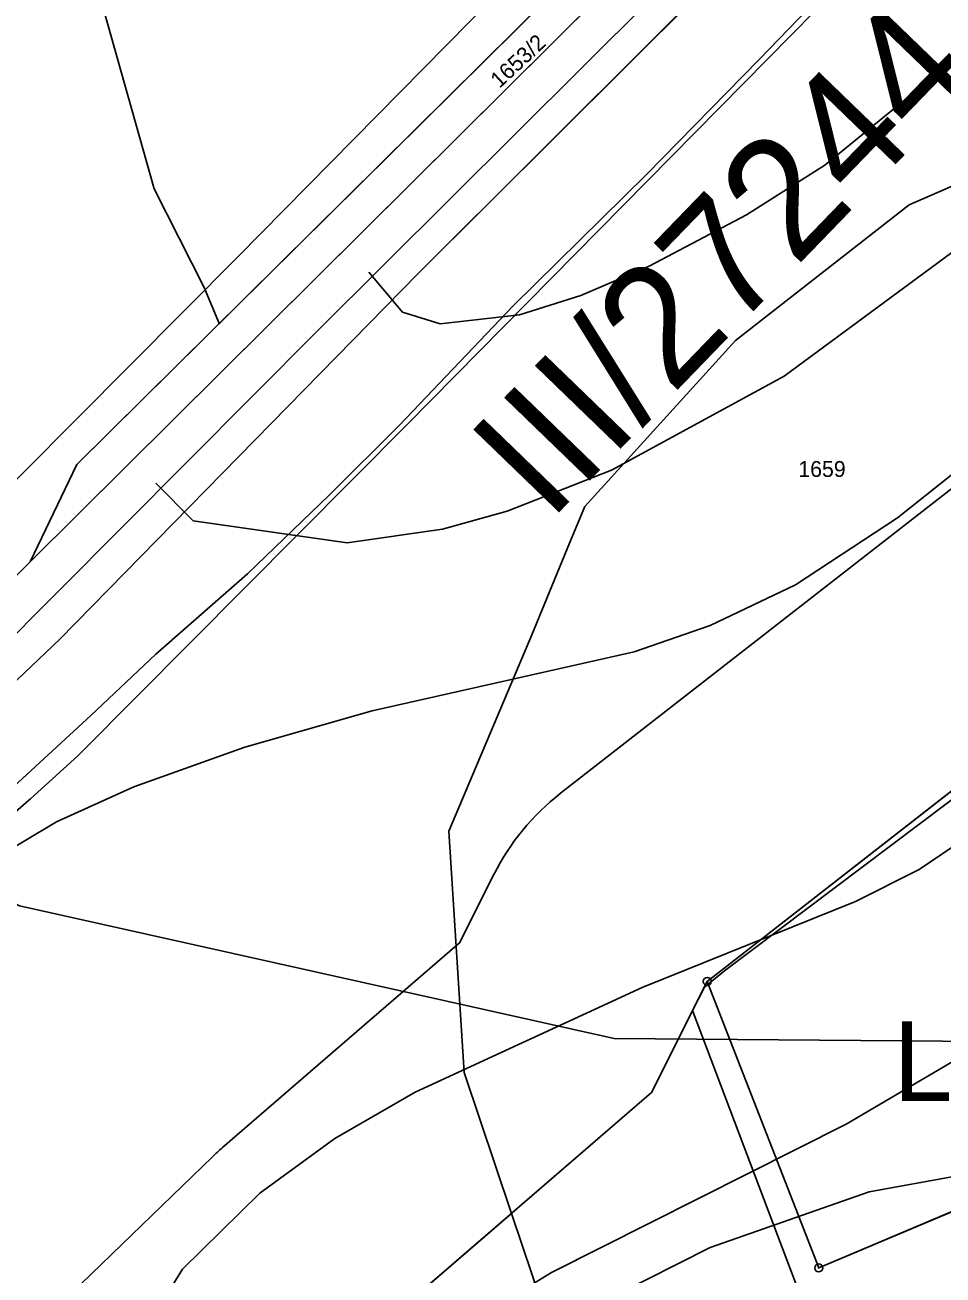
# Model space of a CAD drawing. Extents: x -706130 to -698555, y -971544 to -967260.
# Drawn here: x -704555.8 to -704440.4, y -971375.3 to -971218.1 of the extents above; entities that cross this region are included whole.
import ezdxf

# ---------------------------------------------------------------- set-up
doc = ezdxf.new("R2010")
doc.units = 0
for name, color, linetype in [('BPEJ hranice S', 7, 'Continuous'), ('BPEJ I-II trida ochrany S', 7, 'Continuous'), ('KN_Hranice_parcel', 7, 'Continuous'), ('KN_Parcelni cisla', 7, 'Continuous'), ('KN_Polygon parcely', 7, 'Continuous'), ('KN_POZEMKY_10_LESNI POZEMEK', 7, 'Continuous'), ('KN_POZEMKY_14_OSTATNI PLOCHA', 7, 'Continuous'), ('KN_POZEMKY_2_ORNA PUDA', 7, 'Continuous'), ('KN_VYUZITI_16_ostatni plocha_silnice', 7, 'Continuous'), ('KN_Značky bodu BP', 7, 'Continuous'), ('Komunikace III třídy osy S', 7, 'Continuous'), ('Komunikace popis trid a kategorie popis S', 7, 'Continuous'), ('OP lesa 30 m', 7, 'Continuous'), ('OP silnic S', 7, 'Continuous'), ('Plochy doprava silniční - silnice III třídy S', 7, 'Continuous'), ('Plochy lesní všeobecné S', 7, 'Continuous'), ('Plochy zemědělské všeobecné CELEK S', 7, 'Continuous'), ('Povodi vodniho toku S', 7, 'Continuous'), ('Regulační bloky v krajině S', 7, 'Continuous'), ('Regulační bloky zastavěné S', 7, 'Continuous'), ('Regulační kódy v krajině S', 7, 'Continuous'), ('Spoje_dálkový komunikační kabel S', 7, 'Continuous'), ('Trasy cykloturistické N', 7, 'Continuous'), ('VÝŠKOPIS_vrstevnice doplňková', 7, 'Continuous'), ('VÝŠKOPIS_vrstevnice hlavní', 7, 'Continuous'), ('VÝŠKOPIS_vrstevnice zesílená', 7, 'Continuous')]:
    doc.layers.add(name, color=color, linetype=linetype)

msp = doc.modelspace()

# ---------------------------------------------------------------- linework, layer by layer
at = {"layer": 'BPEJ hranice S'}
for points in [[(-704539.06, -971416.29), (-704539.06, -971416.29), (-704508.14, -971414.82), (-704482.74, -971402.86), (-704494.65, -971367.51), (-704500.62, -971349.8), (-704502.52, -971319.44), (-704492.08, -971294.76), (-704487.34, -971283.24), (-704485.44, -971278.63), (-704466.47, -971257.76), (-704444.65, -971240.68), (-704401.02, -971221.7), (-704353.59, -971203.67)], [(-704378.49, -971271.96), (-704407.01, -971290.68), (-704407.49, -971291.03), (-704409.78, -971292.68), (-704413.99, -971295.73), (-704433.1, -971310.81), (-704467.88, -971337.03), (-704469.91, -971338.68), (-704470.4, -971339.07), (-704471.88, -971342.01), (-704458.27, -971378), (-704455.03, -971389.82), (-704482.74, -971402.86), (-704494.65, -971367.51), (-704500.62, -971349.8), (-704502.52, -971319.44), (-704492.08, -971294.76), (-704487.34, -971283.24), (-704485.44, -971278.63), (-704466.47, -971257.76), (-704444.65, -971240.68), (-704401.02, -971221.7), (-704353.59, -971203.67)], [(-704271.03, -971209.45), (-704281.66, -971219.28), (-704342.87, -971251.11), (-704378.49, -971271.96), (-704407.01, -971290.68), (-704407.49, -971291.03), (-704409.78, -971292.68), (-704413.99, -971295.73), (-704433.1, -971310.81), (-704467.88, -971337.03), (-704469.91, -971338.68), (-704470.4, -971339.07), (-704471.88, -971342.01), (-704458.27, -971378), (-704455.03, -971389.82), (-704482.74, -971402.86), (-704508.14, -971414.82)]]:
    msp.add_lwpolyline(points, dxfattribs=at)
at = {"layer": 'BPEJ I-II trida ochrany S'}
for p, q in [((-704415.53, -971158.66), (-704506.42, -971249.39)), ((-704555.17, -971285.57), (-704441.18, -971172.34)), ((-704506.42, -971249.39), (-704551.5, -971295.37)), ((-704485.44, -971278.63), (-704466.47, -971257.76)), ((-704487.34, -971283.24), (-704485.44, -971278.63)), ((-704492.08, -971294.76), (-704487.34, -971283.24)), ((-704567.91, -971298.24), (-704555.17, -971285.57)), ((-704551.5, -971295.37), (-704580.53, -971322.96)), ((-704494.65, -971367.51), (-704500.62, -971349.8)), ((-704511.39, -971381.95), (-704494.65, -971367.51)), ((-704494.65, -971367.51), (-704494.65, -971367.51))]:
    msp.add_line(p, q, dxfattribs=at)
for points in [[(-704466.47, -971257.76), (-704444.65, -971240.68), (-704401.02, -971221.7), (-704353.59, -971203.67), (-704319.45, -971190.38)], [(-704500.62, -971349.8), (-704502.52, -971319.44), (-704492.08, -971294.76)]]:
    msp.add_lwpolyline(points, dxfattribs=at)
at = {"layer": 'KN_Hranice_parcel'}
for p, q in [((-704555.17, -971285.57), (-704441.18, -971172.34)), ((-704470.04, -971338.35), (-704409.85, -971291.43)), ((-704470.04, -971338.35), (-704456.02, -971374.37)), ((-704456.02, -971374.37), (-704407.76, -971353.94))]:
    msp.add_line(p, q, dxfattribs=at)
for points in [[(-704352.25, -971025.04), (-704354.41, -971041.91), (-704363.75, -971071.95), (-704372.53, -971093.91), (-704392.41, -971128.82), (-704407.11, -971148.63), (-704415.53, -971158.66), (-704506.42, -971249.39), (-704551.5, -971295.37), (-704580.53, -971322.96), (-704605.87, -971343.56)], [(-704441.93, -971167), (-704549.29, -971273.33), (-704555.17, -971285.57)], [(-704609.43, -971335.09), (-704585.77, -971315.95), (-704567.91, -971298.24), (-704555.17, -971285.57)], [(-704547.28, -971416.68), (-704511.39, -971381.95), (-704477.04, -971352.31), (-704470.04, -971338.35)]]:
    msp.add_lwpolyline(points, dxfattribs=at)
at = {"layer": 'KN_Polygon parcely'}
for points in [[(-704609.43, -971335.09), (-704585.77, -971315.95), (-704567.91, -971298.24), (-704555.17, -971285.57), (-704549.29, -971273.33), (-704441.93, -971167), (-704450.89, -971103.61), (-704466.38, -971059.78), (-704480.71, -970987.86), (-704567.32, -971026.96), (-704576.96, -971042.42), (-704567.8, -971056.89), (-704572.05, -971076.18), (-704593.88, -971059.39), (-704608.77, -971071.6), (-704630.27, -971084.33), (-704701.81, -971105.18), (-704664.8, -971185.41), (-704639.88, -971252.78), (-704622.91, -971298.66)], [(-704555.17, -971285.57), (-704441.18, -971172.34), (-704441.93, -971167), (-704549.29, -971273.33)], [(-704456.02, -971374.37), (-704407.76, -971353.94), (-704392.68, -971363.46), (-704385.48, -971359.18), (-704401.24, -971335.95), (-704408.17, -971319.91), (-704409.85, -971291.43), (-704470.04, -971338.35)], [(-704450.76, -971387.81), (-704394.94, -971364.8), (-704392.68, -971363.46), (-704407.76, -971353.94), (-704456.02, -971374.37), (-704470.04, -971338.35), (-704477.04, -971352.31), (-704511.39, -971381.95), (-704547.28, -971416.68), (-704508.14, -971414.82)]]:
    msp.add_lwpolyline(points, close=True, dxfattribs=at)
for points in [[(-704713.64, -971431.41), (-704688.13, -971410.86), (-704605.87, -971343.56), (-704580.53, -971322.96), (-704551.5, -971295.37), (-704506.42, -971249.39), (-704415.53, -971158.66)], [(-704415.53, -971158.66), (-704506.42, -971249.39), (-704551.5, -971295.37), (-704580.53, -971322.96), (-704605.87, -971343.56), (-704603.2, -971350), (-704685.04, -971417.87), (-704682.53, -971423.59), (-704680.3, -971423.01), (-704576.92, -971418.09), (-704547.28, -971416.68), (-704511.39, -971381.95), (-704477.04, -971352.31), (-704470.04, -971338.35), (-704409.85, -971291.43), (-704407.56, -971289.95), (-704347.25, -971251.15), (-704280.58, -971216.79)], [(-704441.18, -971172.34), (-704555.17, -971285.57), (-704567.91, -971298.24), (-704585.77, -971315.95), (-704609.43, -971335.09), (-704624.74, -971347.46), (-704672.66, -971386.8), (-704691.62, -971401.87)]]:
    msp.add_lwpolyline(points, dxfattribs=at)
at = {"layer": 'KN_POZEMKY_10_LESNI POZEMEK'}
for p, q in [((-704470.04, -971338.35), (-704409.85, -971291.43)), ((-704477.04, -971352.31), (-704470.04, -971338.35)), ((-704456.02, -971374.37), (-704470.04, -971338.35)), ((-704470.04, -971338.35), (-704456.02, -971374.37)), ((-704511.39, -971381.95), (-704477.04, -971352.31)), ((-704407.76, -971353.94), (-704456.02, -971374.37)), ((-704456.02, -971374.37), (-704407.76, -971353.94))]:
    msp.add_line(p, q, dxfattribs=at)
at = {"layer": 'KN_POZEMKY_14_OSTATNI PLOCHA'}
for p, q in [((-704415.53, -971158.66), (-704506.42, -971249.39)), ((-704555.17, -971285.57), (-704441.18, -971172.34)), ((-704506.42, -971249.39), (-704551.5, -971295.37)), ((-704567.91, -971298.24), (-704555.17, -971285.57)), ((-704551.5, -971295.37), (-704580.53, -971322.96))]:
    msp.add_line(p, q, dxfattribs=at)
at = {"layer": 'KN_POZEMKY_2_ORNA PUDA'}
for p, q in [((-704506.42, -971249.39), (-704415.53, -971158.66)), ((-704441.93, -971167), (-704549.29, -971273.33)), ((-704549.29, -971273.33), (-704441.93, -971167)), ((-704441.18, -971172.34), (-704555.17, -971285.57)), ((-704551.5, -971295.37), (-704506.42, -971249.39)), ((-704549.29, -971273.33), (-704555.17, -971285.57)), ((-704555.17, -971285.57), (-704549.29, -971273.33)), ((-704555.17, -971285.57), (-704567.91, -971298.24)), ((-704409.85, -971291.43), (-704470.04, -971338.35)), ((-704580.53, -971322.96), (-704551.5, -971295.37)), ((-704470.04, -971338.35), (-704477.04, -971352.31)), ((-704477.04, -971352.31), (-704511.39, -971381.95))]:
    msp.add_line(p, q, dxfattribs=at)
at = {"layer": 'KN_VYUZITI_16_ostatni plocha_silnice'}
for p, q in [((-704415.53, -971158.66), (-704506.42, -971249.39)), ((-704555.17, -971285.57), (-704441.18, -971172.34)), ((-704506.42, -971249.39), (-704551.5, -971295.37)), ((-704567.91, -971298.24), (-704555.17, -971285.57)), ((-704551.5, -971295.37), (-704580.53, -971322.96))]:
    msp.add_line(p, q, dxfattribs=at)
at = {"layer": 'KN_Značky bodu BP'}
for centre, radius in [((-704470.04, -971338.35), 0.5), ((-704470.04, -971338.35), 0.0303), ((-704456.02, -971374.37), 0.5), ((-704456.02, -971374.37), 0.0303)]:
    msp.add_circle(centre, radius, dxfattribs=at)
at = {"layer": 'Komunikace III třídy osy S'}
msp.add_lwpolyline([(-704418.9, -971156.83), (-704519.04, -971256.52), (-704559.93, -971297.63), (-704566.09, -971304.24), (-704582.13, -971319.03), (-704663.56, -971384.54), (-704725.87, -971434.39)], dxfattribs=at)
at = {"layer": 'OP lesa 30 m'}
for p, q in [((-704428.29, -971267.77), (-704488.48, -971314.69)), ((-704532.25, -971360.39), (-704568.14, -971395.12))]:
    msp.add_line(p, q, dxfattribs=at)
msp.add_lwpolyline([(-704496.86, -971324.9), (-704501.17, -971333.51), (-704530.99, -971359.24)], dxfattribs=at)
for centre, start, end in [((-704470.04, -971338.35), 127.9375, 153.3693), ((-704511.39, -971381.95), 130.7903, 134.0589)]:
    msp.add_arc(centre, 30, start, end, dxfattribs=at)
at = {"layer": 'OP silnic S'}
for points in [[(-704429.81, -971146.53), (-704529.07, -971247.22), (-704569.68, -971288.05), (-704575.24, -971293.12), (-704591.76, -971307.53), (-704672.95, -971372.84), (-704735.03, -971422.51)], [(-704691.04, -971425.73), (-704654.17, -971396.24), (-704572.73, -971330.72), (-704572.38, -971330.43), (-704555.39, -971315.61), (-704555.14, -971315.39), (-704549.19, -971309.96), (-704548.67, -971309.46), (-704507.75, -971268.32), (-704408.22, -971167.36)]]:
    msp.add_lwpolyline(points, dxfattribs=at)
at = {"layer": 'Plochy doprava silniční - silnice III třídy S'}
for p, q in [((-704506.42, -971249.39), (-704415.53, -971158.66)), ((-704441.18, -971172.34), (-704555.17, -971285.57)), ((-704551.5, -971295.37), (-704506.42, -971249.39)), ((-704555.17, -971285.57), (-704567.91, -971298.24)), ((-704580.53, -971322.96), (-704551.5, -971295.37))]:
    msp.add_line(p, q, dxfattribs=at)
at = {"layer": 'Plochy lesní všeobecné S'}
for p, q in [((-704409.85, -971291.43), (-704470.04, -971338.35)), ((-704470.04, -971338.35), (-704477.04, -971352.31)), ((-704477.04, -971352.31), (-704511.39, -971381.95))]:
    msp.add_line(p, q, dxfattribs=at)
at = {"layer": 'Plochy zemědělské všeobecné CELEK S'}
for p, q in [((-704555.17, -971285.57), (-704441.18, -971172.34)), ((-704567.91, -971298.24), (-704555.17, -971285.57)), ((-704470.04, -971338.35), (-704409.85, -971291.43)), ((-704551.5, -971295.37), (-704580.53, -971322.96)), ((-704477.04, -971352.31), (-704470.04, -971338.35)), ((-704511.39, -971381.95), (-704477.04, -971352.31))]:
    msp.add_line(p, q, dxfattribs=at)
msp.add_lwpolyline([(-704415.53, -971158.66), (-704506.42, -971249.39), (-704551.5, -971295.37)], dxfattribs=at)
at = {"layer": 'Povodi vodniho toku S'}
for points in [[(-705124.58, -971237.16), (-705066.73, -971282.21), (-705048.17, -971290.72), (-704966.01, -971322.36), (-704912.68, -971324.61), (-704850.01, -971290.77), (-704789.63, -971256.64), (-704724.24, -971255.79), (-704654.65, -971276.47), (-704609.18, -971303.34), (-704556.53, -971328.82), (-704481.76, -971345.51), (-704409.39, -971346.11), (-704397.56, -971340.41), (-704380.79, -971339.95), (-704324.49, -971319.27), (-704295.05, -971305.37)], [(-704295.05, -971305.37), (-704324.49, -971319.27), (-704380.79, -971339.95), (-704397.56, -971340.41), (-704409.39, -971346.11), (-704481.76, -971345.51), (-704556.53, -971328.82), (-704609.18, -971303.34), (-704654.65, -971276.47), (-704724.24, -971255.79), (-704789.63, -971256.64), (-704850.01, -971290.77), (-704912.68, -971324.61), (-704966.01, -971322.36), (-705048.17, -971290.72), (-705066.73, -971282.21), (-705124.58, -971237.16)]]:
    msp.add_lwpolyline(points, dxfattribs=at)
at = {"layer": 'Regulační bloky v krajině S'}
for p, q in [((-704555.17, -971285.57), (-704441.18, -971172.34)), ((-704567.91, -971298.24), (-704555.17, -971285.57)), ((-704409.85, -971291.43), (-704470.04, -971338.35)), ((-704470.04, -971338.35), (-704409.85, -971291.43)), ((-704551.5, -971295.37), (-704580.53, -971322.96)), ((-704470.04, -971338.35), (-704477.04, -971352.31)), ((-704477.04, -971352.31), (-704470.04, -971338.35)), ((-704477.04, -971352.31), (-704511.39, -971381.95)), ((-704511.39, -971381.95), (-704477.04, -971352.31))]:
    msp.add_line(p, q, dxfattribs=at)
msp.add_lwpolyline([(-704415.53, -971158.66), (-704506.42, -971249.39), (-704551.5, -971295.37)], dxfattribs=at)
at = {"layer": 'Regulační bloky zastavěné S'}
for p, q in [((-704506.42, -971249.39), (-704415.53, -971158.66)), ((-704441.18, -971172.34), (-704555.17, -971285.57)), ((-704551.5, -971295.37), (-704506.42, -971249.39)), ((-704555.17, -971285.57), (-704567.91, -971298.24)), ((-704580.53, -971322.96), (-704551.5, -971295.37))]:
    msp.add_line(p, q, dxfattribs=at)
at = {"layer": 'Spoje_dálkový komunikační kabel S'}
msp.add_lwpolyline([(-704448.7, -971207.06), (-704463.53, -971222.43), (-704477.74, -971236.94), (-704494.43, -971253.39), (-704508.73, -971268.38), (-704517.55, -971277.15), (-704527.86, -971287.08), (-704539.36, -971297.2), (-704547.56, -971304.9), (-704564.22, -971320.24), (-704575.54, -971330.2), (-704583.6, -971337.24), (-704601.47, -971351.7), (-704618.68, -971366.35), (-704625.24, -971372.44), (-704633.75, -971380), (-704647.68, -971392.17), (-704661.31, -971404.26), (-704671.37, -971412.4), (-704679.1, -971418.79)], dxfattribs=at)
at = {"layer": 'Trasy cykloturistické N'}
msp.add_lwpolyline([(-704713.64, -971431.41), (-704688.13, -971410.86), (-704605.87, -971343.56), (-704580.53, -971322.96), (-704551.5, -971295.37), (-704506.42, -971249.39), (-704415.53, -971158.66)], dxfattribs=at)
at = {"layer": 'VÝŠKOPIS_vrstevnice doplňková'}
for points in [[(-704429, -971237.69), (-704437.7, -971245.53), (-704460.39, -971262.22), (-704482.07, -971274.07), (-704495.2, -971279.2), (-704503.33, -971281.49), (-704515.31, -971283.2), (-704534.68, -971280.41), (-704539.38, -971275.69)], [(-704410.06, -971371.03), (-704413.02, -971367.09), (-704417.3, -971364.81), (-704422.58, -971363.09), (-704427.57, -971362.52), (-704438.56, -971362.81), (-704449.69, -971364.81), (-704469.66, -971371.8), (-704481.79, -971377.93)]]:
    msp.add_lwpolyline(points, dxfattribs=at)
at = {"layer": 'VÝŠKOPIS_vrstevnice hlavní'}
for points in [[(-704531.35, -971255.68), (-704533.29, -971251.1), (-704539.57, -971238.68), (-704548.27, -971207.87), (-704553.98, -971191.89), (-704559.11, -971181.9), (-704563.39, -971175.91), (-704568.39, -971170.92), (-704576.95, -971164.35), (-704587.22, -971158.79), (-704600.92, -971154.79), (-704609.76, -971153.51), (-704615.47, -971153.37), (-704630.73, -971156.08), (-704641.72, -971159.93), (-704651.57, -971164.64), (-704664.26, -971172.91), (-704687.66, -971191.03), (-704710.06, -971205.3)], [(-704328.99, -971204.02), (-704365.51, -971219.42), (-704379.78, -971227.56), (-704398.32, -971239.54), (-704417.01, -971254.24), (-704434.28, -971270.64), (-704446.12, -971280.06), (-704458.96, -971288.48), (-704469.66, -971293.61), (-704479.22, -971296.89), (-704512.18, -971304.31), (-704528.16, -971308.88), (-704542.14, -971313.87), (-704551.84, -971318.29), (-704564.11, -971325.57), (-704576.66, -971335.99), (-704590.07, -971353.11), (-704595.35, -971361.67), (-704599.06, -971369.94), (-704601.35, -971378.5), (-704602.49, -971387.06), (-704601.49, -971401.33), (-704598.92, -971409.89), (-704594.14, -971418.91)], [(-704257.79, -971206.44), (-704278.34, -971218.14), (-704297.03, -971227.27), (-704349.82, -971249.53), (-704372.93, -971261.37), (-704386.63, -971270.79), (-704396.76, -971278.92), (-704405.74, -971288.05), (-704425.86, -971310.45), (-704436.27, -971319.44), (-704443.41, -971324.29), (-704451.4, -971328.28), (-704478.22, -971339.12), (-704506.75, -971352.25), (-704516.88, -971358.1), (-704526.3, -971364.95), (-704536, -971374.51), (-704541.28, -971383.07), (-704543.42, -971388.2), (-704545.56, -971396.76), (-704545.99, -971401.9), (-704545.42, -971408.75), (-704543.71, -971415.6), (-704543.22, -971416.49)], [(-704426.29, -971211.15), (-704434.99, -971219.14), (-704455.25, -971235.69), (-704465.09, -971241.97), (-704477.36, -971248.39), (-704485.92, -971252.1), (-704493.63, -971254.52), (-704503.62, -971255.66), (-704508.34, -971254.2), (-704512.59, -971249.17)]]:
    msp.add_lwpolyline(points, dxfattribs=at)
at = {"layer": 'VÝŠKOPIS_vrstevnice zesílená'}
msp.add_lwpolyline([(-704079.03, -971030.53), (-704091.87, -971046.22), (-704137.38, -971113.99), (-704149.94, -971131.25), (-704162.92, -971147.66), (-704181.47, -971167.06), (-704200.87, -971184.33), (-704210.57, -971192.03), (-704236.82, -971211.01), (-704253.09, -971221.42), (-704282.76, -971237.97), (-704332.84, -971261.51), (-704355.81, -971274.35), (-704365.94, -971282.2), (-704375.21, -971290.9), (-704394.76, -971315.58), (-704409.74, -971330.28), (-704414.87, -971334.13), (-704452.56, -971356.28), (-704489.63, -971374.93), (-704495.63, -971378.64)], dxfattribs=at)

# ---------------------------------------------------------------- texts
at = {"layer": 'KN_Parcelni cisla'}
msp.add_text('1653/2', height=2, rotation=43, dxfattribs=at).set_placement((-704496.16, -971226.12))
msp.add_text('1659', height=2, dxfattribs=at).set_placement((-704458.59, -971274.91))
at = {"layer": 'Komunikace popis trid a kategorie popis S'}
msp.add_text('III/27244   S 7,5/60', height=15, rotation=45.9672, dxfattribs=at).set_placement((-704489.96, -971280.7))
at = {"layer": 'Regulační kódy v krajině S'}
msp.add_text('LE', height=10, dxfattribs=at).set_placement((-704446.66, -971353.38))

doc.saveas('drawing.dxf')
